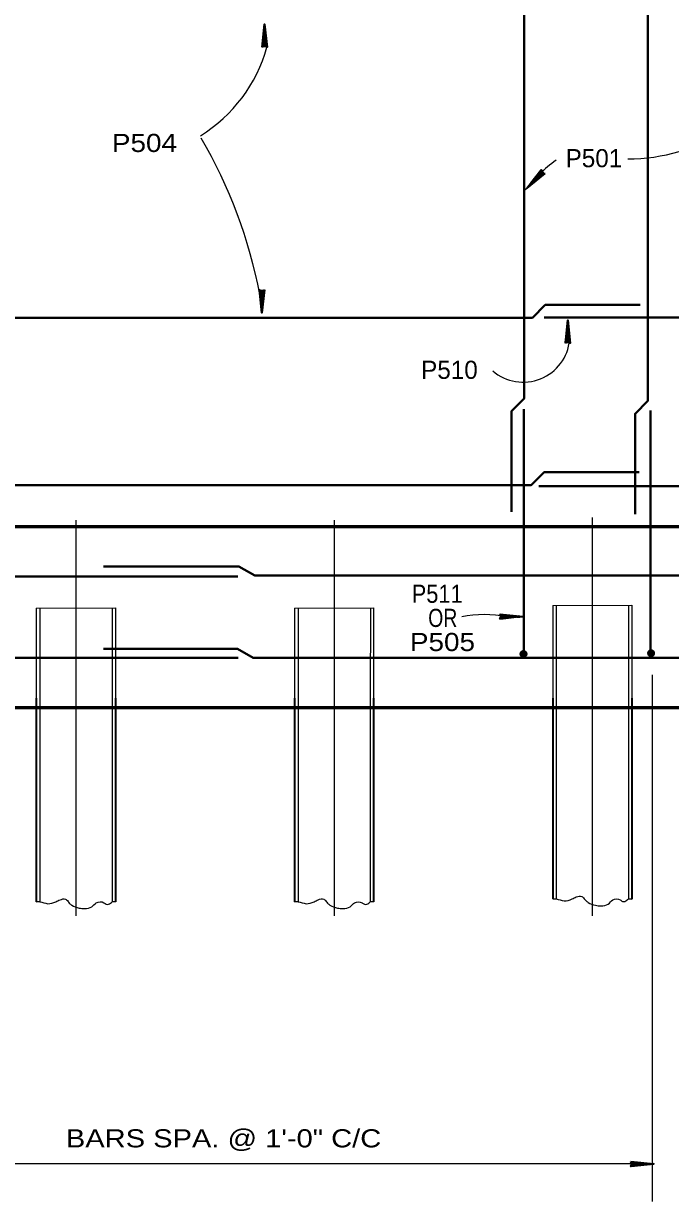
# Model space of a CAD drawing. Extents: x 3.64 to 6.84, y -0.8 to 1.19.
# Drawn here: x 4.234 to 4.532, y -0.369 to 0.172 of the extents above; entities that cross this region are included whole.
import ezdxf

# ---------------------------------------------------------------- set-up
doc = ezdxf.new("R2010")
doc.units = 0
doc.header["$LTSCALE"] = 0.0033
doc.linetypes.add('DOT_DASHED', pattern=[7.7, 5, -1.2, 0.3, -1.2])
doc.linetypes.add('MEDIUM_DASHED', pattern=[4.5, 3, -1.5])
doc.layers.add('1', color=7, linetype='Continuous', lineweight=40)
doc.layers.add('5', color=7, linetype='MEDIUM_DASHED', lineweight=13)

msp = doc.modelspace()

# ---------------------------------------------------------------- linework, layer by layer
at = {"layer": '1', "lineweight": 35}
for p, q in [((4.344, 0.16175), (4.344917, 0.169583)), ((4.344, 0.16175), (4.344917, 0.169583)), ((4.344083, 0.16175), (4.344917, 0.169583)), ((4.344167, 0.16175), (4.345, 0.169583)), ((4.344167, 0.16175), (4.345167, 0.169583)), ((4.345667, 0.161667), (4.344917, 0.169)), ((4.345, 0.1615), (4.345, 0.172083)), ((4.345833, 0.16175), (4.345, 0.169083)), ((4.345917, 0.16175), (4.345167, 0.169083)), ((4.346083, 0.16175), (4.34525, 0.169083)), ((4.473083, 0.10425), (4.465583, 0.09675)), ((4.4735, 0.1035), (4.46725, 0.098667)), ((4.4735, 0.1035), (4.467333, 0.0985)), ((4.4735, 0.103417), (4.467417, 0.098417)), ((4.473583, 0.103333), (4.467417, 0.098417)), ((4.473583, 0.103333), (4.467417, 0.098417)), ((4.472083, 0.104833), (4.4675, 0.099083)), ((4.47225, 0.104667), (4.467583, 0.099)), ((4.472333, 0.104667), (4.467667, 0.098833)), ((4.4725, 0.104583), (4.467833, 0.098833)), ((4.34275, 0.04975), (4.343583, 0.042417)), ((4.342917, 0.04975), (4.343667, 0.042417)), ((4.343, 0.04975), (4.343833, 0.042417)), ((4.343167, 0.049833), (4.343917, 0.0425)), ((4.344667, 0.04975), (4.343667, 0.041917)), ((4.343833, 0.05), (4.343833, 0.039417)), ((4.344667, 0.04975), (4.343833, 0.041917)), ((4.344833, 0.04975), (4.343917, 0.041917)), ((4.344833, 0.04975), (4.343917, 0.041917)), ((4.34475, 0.04975), (4.343917, 0.041917)), ((4.483417, 0.02575), (4.484333, 0.033583)), ((4.483417, 0.02575), (4.484333, 0.033583)), ((4.4835, 0.02575), (4.484333, 0.033583)), ((4.483583, 0.02575), (4.484417, 0.033583)), ((4.483583, 0.02575), (4.484583, 0.033583)), ((4.485083, 0.025667), (4.484333, 0.033)), ((4.484417, 0.0255), (4.484417, 0.036083)), ((4.48525, 0.02575), (4.484417, 0.033083)), ((4.485333, 0.02575), (4.484583, 0.033083)), ((4.4855, 0.02575), (4.484667, 0.033083)), ((4.45325, -0.100083), (4.463833, -0.100083)), ((4.453417, -0.10075), (4.46075, -0.1)), ((4.4535, -0.099083), (4.461333, -0.1)), ((4.4535, -0.099083), (4.461333, -0.1)), ((4.4535, -0.099167), (4.461333, -0.1)), ((4.4535, -0.09925), (4.461333, -0.100083)), ((4.4535, -0.09925), (4.461333, -0.10025)), ((4.4535, -0.100917), (4.460833, -0.100083)), ((4.4535, -0.101), (4.460833, -0.10025)), ((4.4535, -0.101167), (4.460833, -0.100333)), ((4.513333, -0.351667), (4.523917, -0.351667)), ((4.5135, -0.352333), (4.520833, -0.351583)), ((4.513583, -0.350667), (4.521417, -0.351583)), ((4.513583, -0.350667), (4.521417, -0.351583)), ((4.513583, -0.35075), (4.521417, -0.351583)), ((4.513583, -0.350833), (4.521417, -0.351667)), ((4.513583, -0.350833), (4.521417, -0.351833)), ((4.513583, -0.3525), (4.520917, -0.351667)), ((4.513583, -0.352583), (4.520917, -0.351833)), ((4.513583, -0.35275), (4.520917, -0.351917))]:
    msp.add_line(p, q, dxfattribs=at)
at = {"layer": '1'}
for p, q in [((4.4735, 0.03725), (4.589083, 0.03725)), ((4.464167, -0.004917), (4.464167, -0.117417)), ((4.522417, -0.005417), (4.522417, -0.117833)), ((4.471167, -0.040167), (4.588333, -0.040167)), ((4.463417, -0.116167), (4.463083, -0.118167)), ((4.4635, -0.11625), (4.463167, -0.118167)), ((4.463583, -0.11625), (4.46325, -0.118167)), ((4.46475, -0.117583), (4.46325, -0.117417)), ((4.46475, -0.11775), (4.46325, -0.117583)), ((4.46475, -0.117833), (4.46325, -0.11775)), ((4.46475, -0.117833), (4.46325, -0.11775)), ((4.46475, -0.117917), (4.46325, -0.117833)), ((4.46475, -0.118), (4.46325, -0.117917)), ((4.46475, -0.118083), (4.46325, -0.118)), ((4.46475, -0.118167), (4.46325, -0.118083)), ((4.46475, -0.11825), (4.46325, -0.118167)), ((4.46475, -0.118333), (4.46325, -0.11825)), ((4.46475, -0.1185), (4.46325, -0.118417)), ((4.463667, -0.11625), (4.463333, -0.11825)), ((4.464833, -0.116417), (4.463333, -0.116333)), ((4.464833, -0.1165), (4.463333, -0.116417)), ((4.464833, -0.116583), (4.463333, -0.1165)), ((4.464833, -0.116667), (4.463333, -0.116583)), ((4.464833, -0.11675), (4.463333, -0.116667)), ((4.464833, -0.116917), (4.463333, -0.116833)), ((4.464833, -0.117), (4.463333, -0.116917)), ((4.464833, -0.117083), (4.463333, -0.117)), ((4.464833, -0.117167), (4.463333, -0.117083)), ((4.464833, -0.11725), (4.463333, -0.117167)), ((4.464833, -0.117333), (4.463333, -0.11725)), ((4.464833, -0.117417), (4.463333, -0.117333)), ((4.463917, -0.11625), (4.4635, -0.11825)), ((4.464083, -0.116333), (4.463667, -0.11825)), ((4.464167, -0.116333), (4.46375, -0.11825)), ((4.46425, -0.116333), (4.463833, -0.118333)), ((4.464333, -0.116333), (4.464, -0.118333)), ((4.464417, -0.116417), (4.464083, -0.118333)), ((4.464583, -0.116417), (4.464167, -0.118417)), ((4.464667, -0.116417), (4.46425, -0.118417)), ((4.46475, -0.116417), (4.464417, -0.118417)), ((4.464833, -0.116417), (4.4645, -0.118417)), ((4.465, -0.1165), (4.464667, -0.118417)), ((4.522083, -0.115833), (4.52175, -0.117833)), ((4.522167, -0.115917), (4.521833, -0.117833)), ((4.52225, -0.115917), (4.521917, -0.117833)), ((4.523417, -0.11725), (4.521917, -0.117083)), ((4.523417, -0.117417), (4.521917, -0.11725)), ((4.523417, -0.1175), (4.521917, -0.117417)), ((4.523417, -0.1175), (4.521917, -0.117417)), ((4.523417, -0.117583), (4.521917, -0.1175)), ((4.523417, -0.117667), (4.521917, -0.117583)), ((4.523417, -0.11775), (4.521917, -0.117667)), ((4.523417, -0.117833), (4.521917, -0.11775)), ((4.523417, -0.117917), (4.521917, -0.117833)), ((4.523417, -0.118), (4.521917, -0.117917)), ((4.523417, -0.118167), (4.521917, -0.118083)), ((4.522333, -0.115917), (4.522, -0.117917)), ((4.5235, -0.116083), (4.522, -0.116)), ((4.5235, -0.116167), (4.522, -0.116083)), ((4.5235, -0.11625), (4.522, -0.116167)), ((4.5235, -0.116333), (4.522, -0.11625)), ((4.5235, -0.116417), (4.522, -0.116333)), ((4.5235, -0.116583), (4.522, -0.1165)), ((4.5235, -0.116667), (4.522, -0.116583)), ((4.5235, -0.11675), (4.522, -0.116667)), ((4.5235, -0.116833), (4.522, -0.11675)), ((4.5235, -0.116917), (4.522, -0.116833)), ((4.5235, -0.117), (4.522, -0.116917)), ((4.5235, -0.117083), (4.522, -0.117)), ((4.522583, -0.115917), (4.522167, -0.117917)), ((4.52275, -0.116), (4.522333, -0.117917)), ((4.522833, -0.116), (4.522417, -0.117917)), ((4.522917, -0.116), (4.5225, -0.118)), ((4.523, -0.116), (4.522667, -0.118)), ((4.523083, -0.116083), (4.52275, -0.118)), ((4.52325, -0.116083), (4.522833, -0.118083)), ((4.523333, -0.116083), (4.522917, -0.118083)), ((4.523417, -0.116083), (4.523083, -0.118083)), ((4.5235, -0.116083), (4.523167, -0.118083)), ((4.523667, -0.116167), (4.523333, -0.118083))]:
    msp.add_line(p, q, dxfattribs=at)
at = {"layer": '1', "lineweight": 13}
for p, q in [((4.52325, -0.126917), (4.52325, -0.368917)), ((4.1025, -0.3515), (4.522667, -0.3515))]:
    msp.add_line(p, q, dxfattribs=at)
at = {"layer": '1', "lineweight": 60}
msp.add_line((4.694417, -0.142083), (3.944417, -0.142083), dxfattribs=at)
at = {"layer": '1'}
for points in [[(4.4585, 0.252583), (4.4585, 0.214333), (4.464417, 0.208417), (4.464417, 0.000083), (4.4585, -0.005833), (4.4585, -0.052083)], [(4.515333, 0.253167), (4.515333, 0.21325), (4.52125, 0.207333), (4.52125, -0.001), (4.515333, -0.006917), (4.515333, -0.053167)], [(4.51775, 0.043083), (4.474083, 0.043083), (4.468167, 0.037167), (4.253417, 0.037167), (4.1585, 0.037167), (4.152583, 0.043083), (4.10925, 0.043083)], [(4.517167, -0.033833), (4.4735, -0.033833), (4.467583, -0.03975), (4.252833, -0.03975), (4.157917, -0.03975), (4.152, -0.033833), (4.108667, -0.033833)], [(4.270917, -0.077167), (4.33325, -0.077167), (4.3405, -0.081333), (4.675917, -0.081333)], [(3.962833, -0.081667), (4.270917, -0.081667), (4.332667, -0.081667)], [(4.271, -0.114917), (4.332583, -0.114917), (4.339833, -0.119083), (4.67675, -0.119083)], [(4.464, -0.116), (4.464333, -0.118583), (4.464833, -0.11625), (4.46375, -0.118583), (4.463333, -0.116167), (4.463, -0.118167), (4.465083, -0.118167), (4.46275, -0.11725), (4.465333, -0.1175), (4.463, -0.1165), (4.465333, -0.116833), (4.46275, -0.117667), (4.4645, -0.116083), (4.464667, -0.1185), (4.462833, -0.116833), (4.46525, -0.117917), (4.464833, -0.11625), (4.463333, -0.116167), (4.46275, -0.11725), (4.463, -0.118167), (4.46375, -0.118583), (4.464667, -0.1185), (4.46525, -0.117917), (4.464167, -0.11725), (4.46325, -0.118417), (4.463, -0.1165), (4.464167, -0.11725), (4.464667, -0.116167), (4.465333, -0.117167), (4.46425, -0.11725), (4.463, -0.118083), (4.46425, -0.116083), (4.464583, -0.117417), (4.465083, -0.118167)], [(4.522667, -0.115667), (4.523, -0.11825), (4.5235, -0.115917), (4.522417, -0.11825), (4.522, -0.115833), (4.521667, -0.117833), (4.52375, -0.117833), (4.521417, -0.116917), (4.524, -0.117167), (4.521667, -0.116167), (4.524, -0.1165), (4.521417, -0.117333), (4.523167, -0.11575), (4.523333, -0.118167), (4.5215, -0.1165), (4.523917, -0.117583), (4.5235, -0.115917), (4.522, -0.115833), (4.521417, -0.116917), (4.521667, -0.117833), (4.522417, -0.11825), (4.523333, -0.118167), (4.523917, -0.117583), (4.522833, -0.116917), (4.521917, -0.118083), (4.521667, -0.116167), (4.522833, -0.116917), (4.523333, -0.115833), (4.524, -0.116833), (4.522917, -0.116917), (4.521667, -0.11775), (4.522917, -0.11575), (4.52325, -0.117083), (4.52375, -0.117833)], [(3.962, -0.119083), (4.271, -0.119083), (4.332917, -0.119083)]]:
    msp.add_lwpolyline(points, dxfattribs=at)
at = {"layer": '1', "lineweight": 35}
for points in [[(4.343917, 0.1615), (4.345, 0.172083), (4.346167, 0.1615), (4.345, 0.162083)], [(4.344917, 0.16225), (4.344833, 0.166917), (4.344917, 0.166917), (4.344917, 0.166), (4.344833, 0.16225), (4.34475, 0.16525), (4.344667, 0.162083), (4.344583, 0.164333), (4.3445, 0.162083), (4.34475, 0.165583), (4.344917, 0.17025), (4.345167, 0.169333), (4.345167, 0.170583), (4.345167, 0.16225), (4.345333, 0.164667), (4.345333, 0.162083), (4.344917, 0.167417), (4.345583, 0.162083)], [(4.473833, 0.1035), (4.465583, 0.09675), (4.47225, 0.105083), (4.472667, 0.103833)], [(4.472583, 0.103667), (4.469333, 0.10025), (4.46925, 0.100333), (4.469917, 0.101), (4.472667, 0.103583), (4.470583, 0.101417), (4.472917, 0.103583), (4.471333, 0.101917), (4.473, 0.1035), (4.470333, 0.101167), (4.466917, 0.098), (4.467417, 0.098833), (4.4665, 0.097917), (4.472417, 0.103833), (4.470583, 0.10225), (4.472417, 0.104083), (4.468917, 0.1), (4.47225, 0.10425)], [(4.344917, 0.05), (4.343833, 0.039417), (4.342667, 0.05), (4.343833, 0.049417)], [(4.343917, 0.04925), (4.344, 0.044583), (4.343917, 0.044583), (4.343917, 0.0455), (4.344, 0.04925), (4.344083, 0.04625), (4.344167, 0.049417), (4.34425, 0.047167), (4.344333, 0.049417), (4.344083, 0.045917), (4.343917, 0.04125), (4.343667, 0.042167), (4.343667, 0.040917), (4.343667, 0.04925), (4.3435, 0.046833), (4.3435, 0.049417), (4.343917, 0.044083), (4.34325, 0.049417)], [(4.483333, 0.0255), (4.484417, 0.036083), (4.485583, 0.0255), (4.484417, 0.026083)], [(4.484333, 0.02625), (4.48425, 0.030917), (4.484333, 0.030917), (4.484333, 0.03), (4.48425, 0.02625), (4.484167, 0.02925), (4.484083, 0.026083), (4.484, 0.028333), (4.483917, 0.026083), (4.484167, 0.029583), (4.484333, 0.03425), (4.484583, 0.033333), (4.484583, 0.034583), (4.484583, 0.02625), (4.48475, 0.028667), (4.48475, 0.026083), (4.484333, 0.031417), (4.485, 0.026083)], [(4.45325, -0.099), (4.463833, -0.100083), (4.45325, -0.10125), (4.453833, -0.100083)], [(4.454, -0.1), (4.458667, -0.099917), (4.458667, -0.1), (4.45775, -0.1), (4.454, -0.099917), (4.457, -0.099833), (4.453833, -0.09975), (4.456083, -0.099667), (4.453833, -0.099583), (4.457333, -0.099833), (4.462, -0.1), (4.461083, -0.10025), (4.462333, -0.10025), (4.454, -0.10025), (4.456417, -0.100417), (4.453833, -0.100417), (4.459167, -0.1), (4.453833, -0.100667)], [(4.513333, -0.350583), (4.523917, -0.351667), (4.513333, -0.352833), (4.513917, -0.351667)], [(4.514083, -0.351583), (4.51875, -0.3515), (4.51875, -0.351583), (4.517833, -0.351583), (4.514083, -0.3515), (4.517083, -0.351417), (4.513917, -0.351333), (4.516167, -0.35125), (4.513917, -0.351167), (4.517417, -0.351417), (4.522083, -0.351583), (4.521167, -0.351833), (4.522417, -0.351833), (4.514083, -0.351833), (4.5165, -0.352), (4.513917, -0.352), (4.51925, -0.351583), (4.513917, -0.35225)]]:
    msp.add_lwpolyline(points, close=True, dxfattribs=at)
for points in [[(4.344917, 0.16225), (4.344167, 0.161833), (4.344417, 0.162083), (4.34475, 0.16225), (4.344667, 0.1625), (4.344333, 0.162333), (4.345083, 0.162167), (4.345583, 0.162), (4.346, 0.16175)], [(4.472583, 0.103667), (4.473417, 0.103417), (4.473083, 0.103417), (4.47275, 0.1035), (4.472583, 0.10325), (4.472917, 0.103167), (4.4725, 0.103833), (4.472333, 0.10425), (4.472167, 0.10475)], [(4.343917, 0.04925), (4.344667, 0.049667), (4.344417, 0.049417), (4.344083, 0.04925), (4.344167, 0.049), (4.3445, 0.049167), (4.34375, 0.049333), (4.34325, 0.0495), (4.342833, 0.04975)], [(4.484333, 0.02625), (4.483583, 0.025833), (4.483833, 0.026083), (4.484167, 0.02625), (4.484083, 0.0265), (4.48375, 0.026333), (4.4845, 0.026167), (4.485, 0.026), (4.485417, 0.02575)], [(4.454, -0.1), (4.453583, -0.09925), (4.453833, -0.0995), (4.454, -0.099833), (4.45425, -0.09975), (4.454083, -0.099417), (4.453917, -0.100167), (4.45375, -0.100667), (4.4535, -0.101083)], [(4.514083, -0.351583), (4.513667, -0.350833), (4.513917, -0.351083), (4.514083, -0.351417), (4.514333, -0.351333), (4.514167, -0.351), (4.514, -0.35175), (4.513833, -0.35225), (4.513583, -0.352667)]]:
    msp.add_lwpolyline(points, dxfattribs=at)
at = {"layer": '1', "lineweight": 60}
msp.add_lwpolyline([(4.02775, -0.05875), (4.270917, -0.05875), (4.611083, -0.05875)], dxfattribs=at)
at = {"layer": '1'}
for centre in [(4.46405, -0.117333), (4.522717, -0.117)]:
    msp.add_circle(centre, 0.00132, dxfattribs=at)
at = {"layer": '1', "lineweight": 13}
for centre, radius, start, end in [((4.279061, 0.180071), 0.069548, 301.5972, 344.51287), ((4.119006, 0.004923), 0.227904, 10.8527, 30.23025), ((4.512085, 0.192659), 0.082492, 269.94116, 303.17307), ((4.5263, 0.046002), 0.079246, 126.64665, 140.95925), ((4.463916, 0.028969), 0.021425, 229.20279, 354.72583), ((4.445958, -0.152239), 0.052998, 78.8025, 101.1975)]:
    msp.add_arc(centre, radius, start, end, dxfattribs=at)
at = {"layer": '5'}
for p, q in [((4.240083, -0.09625), (4.2765, -0.096167)), ((4.240083, -0.09625), (4.240083, -0.137667)), ((4.24175, -0.096167), (4.241667, -0.137667)), ((4.275, -0.096167), (4.274917, -0.137667)), ((4.2765, -0.096167), (4.2765, -0.137667)), ((4.358833, -0.09625), (4.395167, -0.096167)), ((4.358833, -0.09625), (4.358833, -0.137667)), ((4.3605, -0.096167), (4.360417, -0.137667)), ((4.393667, -0.096167), (4.393583, -0.137667)), ((4.395167, -0.096167), (4.395167, -0.137667)), ((4.4775, -0.095), (4.513833, -0.094917)), ((4.4775, -0.095), (4.4775, -0.137667)), ((4.479083, -0.094917), (4.479, -0.137667)), ((4.512333, -0.094917), (4.51225, -0.137667)), ((4.513833, -0.094917), (4.513833, -0.137667))]:
    msp.add_line(p, q, dxfattribs=at)
at = {"layer": '5', "linetype": 'Continuous', "lineweight": 35}
for p, q in [((4.240083, -0.137667), (4.240083, -0.231167)), ((4.2765, -0.137667), (4.2765, -0.23125)), ((4.358833, -0.137667), (4.358833, -0.231167)), ((4.395167, -0.137667), (4.395167, -0.23125)), ((4.4775, -0.137667), (4.4775, -0.229917)), ((4.513833, -0.137667), (4.513833, -0.23))]:
    msp.add_line(p, q, dxfattribs=at)
at = {"layer": '5', "linetype": 'Continuous'}
for p, q in [((4.241667, -0.137667), (4.241667, -0.231167)), ((4.274917, -0.137667), (4.274917, -0.231167)), ((4.360417, -0.137667), (4.360417, -0.231167)), ((4.393583, -0.137667), (4.393583, -0.231167)), ((4.479, -0.137667), (4.479, -0.229917)), ((4.51225, -0.137667), (4.51225, -0.229917))]:
    msp.add_line(p, q, dxfattribs=at)
at = {"layer": '5', "linetype": 'DOT_DASHED'}
for points in [[(4.25825, -0.055833), (4.25825, -0.137667), (4.258333, -0.261833)], [(4.377, -0.055833), (4.377, -0.137667), (4.377, -0.261833)], [(4.495583, -0.054583), (4.495583, -0.137667), (4.495667, -0.260583)]]:
    msp.add_lwpolyline(points, dxfattribs=at)
at = {"layer": '5', "linetype": 'Continuous'}
for points in [[(4.240083, -0.231167), (4.241667, -0.231167), (4.245333, -0.232083), (4.249, -0.231167), (4.251, -0.230333), (4.2535, -0.23), (4.254, -0.230333), (4.25525, -0.231833), (4.256333, -0.23275), (4.25975, -0.234083), (4.26225, -0.234333), (4.265583, -0.2335), (4.267667, -0.231667), (4.271167, -0.231667), (4.272167, -0.232333), (4.27425, -0.231833), (4.274917, -0.231167), (4.2765, -0.23125)], [(4.358833, -0.231167), (4.360417, -0.231167), (4.364083, -0.232083), (4.36775, -0.231167), (4.369667, -0.230333), (4.37225, -0.23), (4.372667, -0.230333), (4.374, -0.231833), (4.375083, -0.23275), (4.3785, -0.234083), (4.381, -0.234333), (4.384333, -0.2335), (4.386417, -0.231667), (4.389833, -0.231667), (4.390917, -0.232333), (4.392917, -0.231833), (4.393583, -0.231167), (4.395167, -0.23125)], [(4.4775, -0.229917), (4.479, -0.229917), (4.48275, -0.230833), (4.486417, -0.229917), (4.488333, -0.229), (4.490917, -0.22875), (4.491333, -0.229083), (4.492583, -0.2305), (4.49375, -0.2315), (4.497083, -0.232833), (4.499667, -0.233083), (4.503, -0.23225), (4.505083, -0.230333), (4.5085, -0.230333), (4.509583, -0.231083), (4.511583, -0.2305), (4.51225, -0.229917), (4.513833, -0.23)]]:
    msp.add_spline(points, degree=3, dxfattribs=at)

# ---------------------------------------------------------------- texts
at = {"layer": '1'}
for s, width, p in [('P504', 1.15, (4.274833, 0.113333)), ('P511', 0.9, (4.412667, -0.093833)), ('OR', 0.8, (4.42025, -0.104917)), ('P505', 1.15, (4.411833, -0.116)), ('BARS SPA. @ 1\'-0" C/C', 1.2, (4.253667, -0.344083))]:
    msp.add_text(s, height=0.008334, dxfattribs=dict(at, width=width)).set_placement(p)
for s, p in [('P501', (4.483417, 0.106333)), ('P510', (4.417, 0.009083))]:
    msp.add_text(s, height=0.008334, dxfattribs=at).set_placement(p)

doc.saveas('drawing.dxf')
